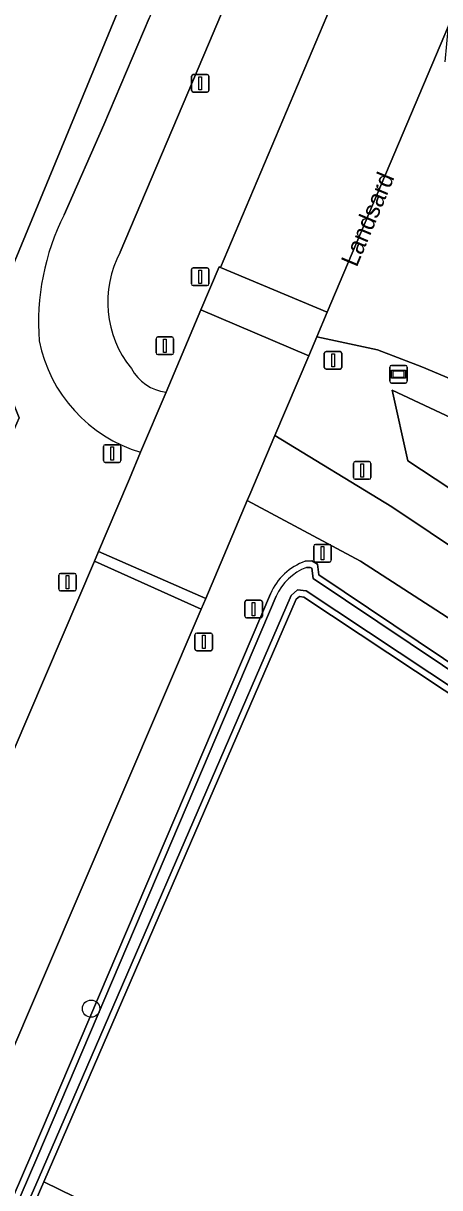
# Model space of a CAD drawing. Extents: x 155209 to 156748, y 385356 to 388487.
# Drawn here: x 155999.5 to 156023.1, y 386144.1 to 386210 of the extents above; entities that cross this region are included whole.
import ezdxf

# ---------------------------------------------------------------- set-up
doc = ezdxf.new("R2010")
doc.units = 0
for name, color, linetype in [('IMGEO_Berm_groen', 7, 'Continuous'), ('IMGEO_Boom', 7, 'Continuous'), ('IMGEO_Erf', 7, 'Continuous'), ('IMGEO_Fietspad_gesloten', 7, 'Continuous'), ('IMGEO_Groenvoorziening', 7, 'Continuous'), ('IMGEO_Hek', 7, 'Continuous'), ('IMGEO_Lichtmast', 7, 'Continuous'), ('IMGEO_Loofbos', 7, 'Continuous'), ('IMGEO_Naaldbos', 7, 'Continuous'), ('IMGEO_Oever', 7, 'Continuous'), ('IMGEO_Openbare_ruimte_label', 7, 'Continuous'), ('IMGEO_Rijbaan_lokaal_gesloten', 7, 'Continuous'), ('IMGEO_Rijbaan_lokaal_open', 7, 'Continuous'), ('IMGEO_Straatnaambord', 7, 'Continuous'), ('IMGEO_Verkeersbordpaal', 7, 'Continuous'), ('IMGEO_Waterloop', 7, 'Continuous')]:
    doc.layers.add(name, color=color, linetype=linetype)

msp = doc.modelspace()

# ---------------------------------------------------------------- linework, layer by layer
at = {"layer": 'IMGEO_Berm_groen'}
for points in [[(156017.719, 386241.801), (155997.339, 386192.467), (155999.279, 386187.649), (155999.017, 386187.05), (155959.302, 386096.168), (155916.981, 385994.929), (155916.273, 385993.234), (155920.084, 385991.513), (155920.814, 385993.21), (155925.378, 386003.819), (155927.744, 386002.822), (155959.53, 386076.883), (155989.702, 386147.215), (156003.535, 386179.533)], [(156001.816, 386199.144), (156004.066, 386204.243), (156006.628, 386210.275)], [(156067.725, 386171.243), (156063.134, 386173.252), (156022.073, 386190.539), (156019.563, 386191.511), (156016.121, 386192.247), (156015.665, 386191.171), (156013.752, 386186.657), (156020.382, 386182.613), (156026.946, 386178.211), (156056.89, 386158.505), (156068.33, 386150.873), (156070.659, 386149.306), (156072.014, 386151.81), (156034.567, 386176.468), (156033.731, 386175.202), (156032.227, 386176.195), (156033.061, 386177.459), (156021.284, 386185.214), (156020.389, 386189.219)], [(156020.389, 386189.219), (156031.664, 386183.929), (156073.255, 386164.351), (156077.439, 386161.836), (156079.419, 386165.495)], [(156003.535, 386179.533), (156003.773, 386180.094), (156004.801, 386182.521), (156005.515, 386184.205), (156006.15, 386185.705)], [(156049.551, 386158.857), (156049.349, 386159.56), (156025.311, 386175.189), (156018.608, 386179.531), (156012.192, 386182.976), (156009.838, 386177.421), (156009.585, 386176.823), (155984.914, 386119.233), (155965.644, 386074.344), (155949.137, 386035.922), (155952.015, 386034.682), (156000, 386146.004)], [(156015.467, 386179.533), (156015.839, 386179.549), (156016.169, 386179.377), (156016.248, 386178.762), (156028.926, 386170.26), (156049.296, 386156.966), (156049.474, 386156.85)], [(156000, 386146.004), (156013.501, 386177.695)]]:
    msp.add_lwpolyline(points, dxfattribs=at)
for centre, radius, start, end in [((156014.042, 386193.021), 13.673, 153.3985, 184.23817), ((156008.54, 386193.651), 8.298, 191.40063, 253.2588), ((156016.601, 386176.349), 3.38, 109.60897, 156.53662)]:
    msp.add_arc(centre, radius, start, end, dxfattribs=at)
at = {"layer": 'IMGEO_Boom'}
msp.add_circle((156003.346, 386154.198), 0.489, dxfattribs=at)
at = {"layer": 'IMGEO_Erf'}
msp.add_lwpolyline([(156066.005, 386142.456), (156065.663, 386144.592), (156050.195, 386154.65), (156050.562, 386155.229), (156050.971, 386155.873), (156050.765, 386156.008), (156050.72, 386155.966), (156049.405, 386156.687), (156049.474, 386156.85), (156049.296, 386156.966), (156048.886, 386156.32), (156048.518, 386155.741), (156032.854, 386165.927), (156015.392, 386177.509), (156015.147, 386177.545), (156014.962, 386177.381), (156000.676, 386144.39), (156006.735, 386141.433)], dxfattribs=at)
at = {"layer": 'IMGEO_Fietspad_gesloten'}
for points in [[(156139.321, 386522.401), (156125.525, 386490.134), (156111.258, 386456.764), (156087.976, 386402.172), (156066.589, 386351.85), (156054.716, 386323.807), (156054.538, 386323.386), (156042.977, 386296.079), (156023.427, 386249.93), (156022.289, 386247.244), (156019.639, 386240.989), (156006.628, 386210.275), (156004.066, 386204.243), (156001.816, 386199.144)], [(156004.996, 386197.039), (156010.003, 386208.816), (156023.008, 386239.564), (156046.408, 386294.89), (156058.063, 386322.415), (156069.84, 386350.227), (156091.234, 386400.622), (156114.612, 386455.401), (156142.588, 386521.008)], [(156006.15, 386185.705), (156007.591, 386189.104)]]:
    msp.add_lwpolyline(points, dxfattribs=at)
for centre, radius, start, end in [((156014.042, 386193.021), 13.673, 153.3985, 184.23817), ((156010.253, 386194.215), 5.968, 151.75594, 219.16082), ((156008.54, 386193.651), 8.298, 191.40063, 253.2588), ((156007.906, 386191.675), 2.59, 208.32341, 263.01421)]:
    msp.add_arc(centre, radius, start, end, dxfattribs=at)
at = {"layer": 'IMGEO_Groenvoorziening'}
for points in [[(156007.591, 386189.104), (156009.569, 386193.772), (156010.599, 386196.203), (156010.669, 386196.174), (156028.113, 386237.404), (156051.194, 386291.958), (156074.965, 386348.058), (156088.146, 386379.283), (156100.534, 386408.284), (156128.809, 386474.423), (156158.862, 386544.699), (156160.628, 386548.864)], [(156142.588, 386521.008), (156114.612, 386455.401), (156091.234, 386400.622), (156069.84, 386350.227), (156058.063, 386322.415), (156046.408, 386294.89), (156023.008, 386239.564), (156010.003, 386208.816), (156004.996, 386197.039)]]:
    msp.add_lwpolyline(points, dxfattribs=at)
msp.add_lwpolyline([(156031.664, 386183.929), (156020.389, 386189.219), (156021.284, 386185.214), (156033.061, 386177.459), (156033.106, 386177.526), (156034.61, 386176.533), (156034.567, 386176.468), (156072.014, 386151.81), (156073.332, 386154.247), (156077.439, 386161.836), (156073.255, 386164.351)], close=True, dxfattribs=at)
for centre, radius, start, end in [((156010.253, 386194.215), 5.968, 151.75594, 219.16082), ((156007.906, 386191.675), 2.59, 208.32341, 263.01421)]:
    msp.add_arc(centre, radius, start, end, dxfattribs=at)
at = {"layer": 'IMGEO_Hek'}
msp.add_lwpolyline([(155979.683, 386081.47), (155987.477, 386099.578), (156000, 386126.796), (156006.735, 386141.433), (156000.676, 386144.39)], dxfattribs=at)
at = {"layer": 'IMGEO_Lichtmast'}
for p, q in [((156009.031, 386206.195), (156009.031, 386206.995)), ((156009.031, 386206.995), (156009.031, 386206.195)), ((156009.131, 386207.095), (156009.921, 386207.095)), ((156009.921, 386207.095), (156009.131, 386207.095)), ((156010.021, 386206.995), (156010.021, 386206.195)), ((156010.021, 386206.195), (156010.021, 386206.995)), ((156009.921, 386206.095), (156009.131, 386206.095)), ((156009.131, 386206.095), (156009.921, 386206.095)), ((156012.053, 386176.426), (156012.053, 386177.226)), ((156012.053, 386177.226), (156012.053, 386176.426)), ((156012.153, 386177.326), (156012.943, 386177.326)), ((156012.943, 386177.326), (156012.153, 386177.326)), ((156013.043, 386177.226), (156013.043, 386176.426)), ((156013.043, 386176.426), (156013.043, 386177.226)), ((156012.943, 386176.326), (156012.153, 386176.326)), ((156012.153, 386176.326), (156012.943, 386176.326))]:
    msp.add_line(p, q, dxfattribs=at)
for points in [[(156009.451, 386206.97), (156009.601, 386206.97), (156009.601, 386206.22), (156009.451, 386206.22), (156009.451, 386206.97)], [(156012.473, 386177.201), (156012.623, 386177.201), (156012.623, 386176.451), (156012.473, 386176.451), (156012.473, 386177.201)]]:
    msp.add_lwpolyline(points, dxfattribs=at)
for centre, start, end in [((156009.131, 386206.995), 90, 180), ((156009.131, 386206.995), 90, 180), ((156009.921, 386206.995), 0, 90), ((156009.921, 386206.995), 360, 90), ((156009.131, 386206.195), 180, 270), ((156009.131, 386206.195), 180, 270), ((156009.921, 386206.195), 270, 0), ((156009.921, 386206.195), 270, 0), ((156012.153, 386177.226), 90, 180), ((156012.153, 386177.226), 90, 180), ((156012.943, 386177.226), 0, 90), ((156012.943, 386177.226), 360, 90), ((156012.153, 386176.426), 180, 270), ((156012.153, 386176.426), 180, 270), ((156012.943, 386176.426), 270, 0), ((156012.943, 386176.426), 270, 0)]:
    msp.add_arc(centre, 0.1, start, end, dxfattribs=at)
at = {"layer": 'IMGEO_Loofbos'}
msp.add_lwpolyline([(155999.017, 386187.05), (155999.279, 386187.649), (155997.339, 386192.467), (156017.719, 386241.801), (156020.329, 386248.119), (156016.112, 386250), (156000, 386257.19), (155899.336, 386302.109), (155849.188, 386325.166), (155836.76, 386296.062), (155825.154, 386268.112)], dxfattribs=at)
at = {"layer": 'IMGEO_Naaldbos'}
msp.add_lwpolyline([(155979.683, 386081.47), (155987.477, 386099.578), (156000, 386126.796), (156006.735, 386141.433), (156000.676, 386144.39), (156000, 386142.83), (155975.488, 386085.88), (155975.714, 386085.504)], close=True, dxfattribs=at)
at = {"layer": 'IMGEO_Oever'}
for points in [[(156000, 386142.83), (156000.676, 386144.39), (156014.962, 386177.381), (156015.147, 386177.545), (156015.392, 386177.509), (156032.854, 386165.927), (156048.518, 386155.741), (156048.886, 386156.32), (156049.296, 386156.966), (156028.926, 386170.26), (156016.248, 386178.762), (156016.169, 386179.377), (156015.839, 386179.549), (156015.467, 386179.533)], [(156015.538, 386179.179), (156015.759, 386179.188), (156015.839, 386179.147), (156015.914, 386178.556), (156028.729, 386169.962), (156048.806, 386156.86), (156048.585, 386156.512), (156048.41, 386156.237), (156033.05, 386166.225), (156015.523, 386177.851), (156015.034, 386177.922), (156014.666, 386177.596), (156000.348, 386144.532), (155999.672, 386142.972), (155975.088, 386085.853), (155975.313, 386085.477), (155942.794, 386010.259)], [(156013.501, 386177.695), (156000, 386146.004), (155952.015, 386034.682), (155941.599, 386010.515), (155942.719, 386009.186), (155975.714, 386085.504), (155975.488, 386085.88), (156000, 386142.83)], [(155942.794, 386010.259), (155942.162, 386010.92), (156000.328, 386145.863), (156013.829, 386177.554)]]:
    msp.add_lwpolyline(points, dxfattribs=at)
for centre, radius, start, end in [((156016.601, 386176.349), 3.38, 109.60897, 156.53662), ((156016.617, 386176.333), 3.044, 110.76625, 156.34723)]:
    msp.add_arc(centre, radius, start, end, dxfattribs=at)
at = {"layer": 'IMGEO_Rijbaan_lokaal_gesloten'}
for points in [[(156160.628, 386548.864), (156158.862, 386544.699), (156128.809, 386474.423), (156100.534, 386408.284), (156088.146, 386379.283), (156074.965, 386348.058), (156051.194, 386291.958), (156028.113, 386237.404), (156010.669, 386196.174), (156016.712, 386193.643), (156023.573, 386209.847), (156034.159, 386234.847), (156057.345, 386289.662), (156080.926, 386345.397), (156094.197, 386376.746), (156106.547, 386405.649)], [(156023.385, 386207.816), (156023.573, 386209.847), (156016.712, 386193.643), (156016.121, 386192.247), (156019.563, 386191.511), (156022.073, 386190.539), (156063.134, 386173.252), (156067.725, 386171.243)], [(156148.477, 386094.745), (156078.082, 386144.223), (156076.416, 386145.394), (156074.85, 386146.487), (156073.573, 386147.346), (156070.659, 386149.306), (156068.33, 386150.873), (156056.89, 386158.505), (156026.946, 386178.211), (156020.382, 386182.613), (156013.752, 386186.657), (156012.339, 386183.322), (156012.192, 386182.976), (156018.608, 386179.531), (156025.311, 386175.189), (156049.349, 386159.56), (156053.498, 386156.729), (156055.217, 386155.797), (156067.905, 386147.283), (156068.865, 386146.585), (156072.75, 386143.917)], [(155944.241, 386024.526), (155949.137, 386035.922), (155965.644, 386074.344), (155984.914, 386119.233), (156009.585, 386176.823), (156003.535, 386179.533), (155989.702, 386147.215), (155959.53, 386076.883), (155927.744, 386002.822), (155923, 385991.79), (155918.964, 385982.464), (155913.394, 385969.476), (155908.982, 385959.227), (155875.912, 385882.637)]]:
    msp.add_lwpolyline(points, dxfattribs=at)
at = {"layer": 'IMGEO_Rijbaan_lokaal_open'}
for points in [[(156010.669, 386196.174), (156010.599, 386196.203), (156009.569, 386193.772), (156015.665, 386191.171), (156016.121, 386192.247), (156016.712, 386193.643)], [(156013.752, 386186.657), (156015.665, 386191.171), (156009.569, 386193.772), (156007.591, 386189.104), (156006.15, 386185.705), (156005.515, 386184.205), (156004.801, 386182.521), (156003.773, 386180.094), (156009.838, 386177.421), (156012.192, 386182.976), (156012.339, 386183.322)], [(156003.773, 386180.094), (156003.535, 386179.533), (156009.585, 386176.823), (156009.838, 386177.421)]]:
    msp.add_lwpolyline(points, close=True, dxfattribs=at)
at = {"layer": 'IMGEO_Straatnaambord'}
for p, q in [((156020.256, 386189.723), (156020.256, 386190.523)), ((156020.256, 386190.523), (156020.256, 386189.723)), ((156020.356, 386190.623), (156021.146, 386190.623)), ((156021.146, 386190.623), (156020.356, 386190.623)), ((156021.246, 386190.523), (156021.246, 386189.723)), ((156021.246, 386189.723), (156021.246, 386190.523)), ((156021.146, 386189.623), (156020.356, 386189.623)), ((156020.356, 386189.623), (156021.146, 386189.623))]:
    msp.add_line(p, q, dxfattribs=at)
for points in [[(156020.357, 386190.355), (156021.145, 386190.355), (156021.145, 386189.891), (156020.357, 386189.891), (156020.357, 386190.355)], [(156020.422, 386190.29), (156020.422, 386189.956), (156021.08, 386189.956), (156021.08, 386190.29), (156020.422, 386190.29)]]:
    msp.add_lwpolyline(points, dxfattribs=at)
for centre, start, end in [((156020.356, 386190.523), 90, 180), ((156020.356, 386190.523), 90, 180), ((156021.146, 386190.523), 0, 90), ((156021.146, 386190.523), 360, 90), ((156020.356, 386189.723), 180, 270), ((156020.356, 386189.723), 180, 270), ((156021.146, 386189.723), 270, 0), ((156021.146, 386189.723), 270, 0)]:
    msp.add_arc(centre, 0.1, start, end, dxfattribs=at)
at = {"layer": 'IMGEO_Verkeersbordpaal'}
for p, q in [((156009.029, 386195.244), (156009.029, 386196.044)), ((156009.029, 386196.044), (156009.029, 386195.244)), ((156009.129, 386196.144), (156009.919, 386196.144)), ((156009.919, 386196.144), (156009.129, 386196.144)), ((156010.019, 386196.044), (156010.019, 386195.244)), ((156010.019, 386195.244), (156010.019, 386196.044)), ((156009.919, 386195.144), (156009.129, 386195.144)), ((156009.129, 386195.144), (156009.919, 386195.144)), ((156007.025, 386191.334), (156007.025, 386192.134)), ((156007.025, 386192.134), (156007.025, 386191.334)), ((156007.125, 386192.234), (156007.915, 386192.234)), ((156007.915, 386192.234), (156007.125, 386192.234)), ((156008.015, 386192.134), (156008.015, 386191.334)), ((156008.015, 386191.334), (156008.015, 386192.134)), ((156016.65, 386191.41), (156017.44, 386191.41)), ((156017.44, 386191.41), (156016.65, 386191.41)), ((156007.915, 386191.234), (156007.125, 386191.234)), ((156007.125, 386191.234), (156007.915, 386191.234)), ((156016.55, 386190.51), (156016.55, 386191.31)), ((156016.55, 386191.31), (156016.55, 386190.51)), ((156017.54, 386191.31), (156017.54, 386190.51)), ((156017.54, 386190.51), (156017.54, 386191.31)), ((156017.44, 386190.41), (156016.65, 386190.41)), ((156016.65, 386190.41), (156017.44, 386190.41)), ((156004.147, 386186.134), (156004.937, 386186.134)), ((156004.937, 386186.134), (156004.147, 386186.134)), ((156004.047, 386185.234), (156004.047, 386186.034)), ((156004.047, 386186.034), (156004.047, 386185.234)), ((156005.037, 386186.034), (156005.037, 386185.234)), ((156005.037, 386185.234), (156005.037, 386186.034)), ((156004.937, 386185.134), (156004.147, 386185.134)), ((156004.147, 386185.134), (156004.937, 386185.134)), ((156018.196, 386184.277), (156018.196, 386185.077)), ((156018.196, 386185.077), (156018.196, 386184.277)), ((156018.296, 386185.177), (156019.086, 386185.177)), ((156019.086, 386185.177), (156018.296, 386185.177)), ((156019.186, 386185.077), (156019.186, 386184.277)), ((156019.186, 386184.277), (156019.186, 386185.077)), ((156019.086, 386184.177), (156018.296, 386184.177)), ((156018.296, 386184.177), (156019.086, 386184.177)), ((156015.953, 386179.59), (156015.953, 386180.39)), ((156015.953, 386180.39), (156015.953, 386179.59)), ((156016.053, 386180.49), (156016.843, 386180.49)), ((156016.843, 386180.49), (156016.053, 386180.49)), ((156016.943, 386180.39), (156016.943, 386179.59)), ((156016.943, 386179.59), (156016.943, 386180.39)), ((156016.843, 386179.49), (156016.053, 386179.49)), ((156016.053, 386179.49), (156016.843, 386179.49)), ((156001.614, 386178.849), (156002.404, 386178.849)), ((156002.404, 386178.849), (156001.614, 386178.849)), ((156001.514, 386177.949), (156001.514, 386178.749)), ((156001.514, 386178.749), (156001.514, 386177.949)), ((156002.504, 386178.749), (156002.504, 386177.949)), ((156002.504, 386177.949), (156002.504, 386178.749)), ((156002.404, 386177.849), (156001.614, 386177.849)), ((156001.614, 386177.849), (156002.404, 386177.849)), ((156009.227, 386174.564), (156009.227, 386175.364)), ((156009.227, 386175.364), (156009.227, 386174.564)), ((156009.327, 386175.464), (156010.117, 386175.464)), ((156010.117, 386175.464), (156009.327, 386175.464)), ((156010.217, 386175.364), (156010.217, 386174.564)), ((156010.217, 386174.564), (156010.217, 386175.364)), ((156010.117, 386174.464), (156009.327, 386174.464)), ((156009.327, 386174.464), (156010.117, 386174.464))]:
    msp.add_line(p, q, dxfattribs=at)
for points in [[(156009.449, 386196.019), (156009.599, 386196.019), (156009.599, 386195.269), (156009.449, 386195.269), (156009.449, 386196.019)], [(156007.445, 386192.109), (156007.595, 386192.109), (156007.595, 386191.359), (156007.445, 386191.359), (156007.445, 386192.109)], [(156016.97, 386191.285), (156017.12, 386191.285), (156017.12, 386190.535), (156016.97, 386190.535), (156016.97, 386191.285)], [(156004.467, 386186.009), (156004.617, 386186.009), (156004.617, 386185.259), (156004.467, 386185.259), (156004.467, 386186.009)], [(156018.616, 386185.052), (156018.766, 386185.052), (156018.766, 386184.302), (156018.616, 386184.302), (156018.616, 386185.052)], [(156016.373, 386180.365), (156016.523, 386180.365), (156016.523, 386179.615), (156016.373, 386179.615), (156016.373, 386180.365)], [(156001.934, 386178.724), (156002.084, 386178.724), (156002.084, 386177.974), (156001.934, 386177.974), (156001.934, 386178.724)], [(156009.647, 386175.339), (156009.797, 386175.339), (156009.797, 386174.589), (156009.647, 386174.589), (156009.647, 386175.339)]]:
    msp.add_lwpolyline(points, dxfattribs=at)
for centre, start, end in [((156009.129, 386196.044), 90, 180), ((156009.129, 386196.044), 90, 180), ((156009.919, 386196.044), 0, 90), ((156009.919, 386196.044), 360, 90), ((156009.129, 386195.244), 180, 270), ((156009.129, 386195.244), 180, 270), ((156009.919, 386195.244), 270, 0), ((156009.919, 386195.244), 270, 0), ((156007.125, 386192.134), 90, 180), ((156007.125, 386192.134), 90, 180), ((156007.915, 386192.134), 0, 90), ((156007.915, 386192.134), 360, 90), ((156016.65, 386191.31), 90, 180), ((156016.65, 386191.31), 90, 180), ((156017.44, 386191.31), 0, 90), ((156017.44, 386191.31), 360, 90), ((156007.125, 386191.334), 180, 270), ((156007.125, 386191.334), 180, 270), ((156007.915, 386191.334), 270, 0), ((156007.915, 386191.334), 270, 0), ((156016.65, 386190.51), 180, 270), ((156016.65, 386190.51), 180, 270), ((156017.44, 386190.51), 270, 0), ((156017.44, 386190.51), 270, 0), ((156004.147, 386186.034), 90, 180), ((156004.147, 386186.034), 90, 180), ((156004.937, 386186.034), 0, 90), ((156004.937, 386186.034), 360, 90), ((156004.147, 386185.234), 180, 270), ((156004.147, 386185.234), 180, 270), ((156004.937, 386185.234), 270, 0), ((156004.937, 386185.234), 270, 0), ((156018.296, 386185.077), 90, 180), ((156018.296, 386185.077), 90, 180), ((156019.086, 386185.077), 0, 90), ((156019.086, 386185.077), 360, 90), ((156018.296, 386184.277), 180, 270), ((156018.296, 386184.277), 180, 270), ((156019.086, 386184.277), 270, 0), ((156019.086, 386184.277), 270, 0), ((156016.053, 386180.39), 90, 180), ((156016.053, 386180.39), 90, 180), ((156016.843, 386180.39), 0, 90), ((156016.843, 386180.39), 360, 90), ((156016.053, 386179.59), 180, 270), ((156016.053, 386179.59), 180, 270), ((156016.843, 386179.59), 270, 0), ((156016.843, 386179.59), 270, 0), ((156001.614, 386178.749), 90, 180), ((156001.614, 386178.749), 90, 180), ((156002.404, 386178.749), 0, 90), ((156002.404, 386178.749), 360, 90), ((156001.614, 386177.949), 180, 270), ((156001.614, 386177.949), 180, 270), ((156002.404, 386177.949), 270, 0), ((156002.404, 386177.949), 270, 0), ((156009.327, 386175.364), 90, 180), ((156009.327, 386175.364), 90, 180), ((156010.117, 386175.364), 0, 90), ((156010.117, 386175.364), 360, 90), ((156009.327, 386174.564), 180, 270), ((156009.327, 386174.564), 180, 270), ((156010.117, 386174.564), 270, 0), ((156010.117, 386174.564), 270, 0)]:
    msp.add_arc(centre, 0.1, start, end, dxfattribs=at)
at = {"layer": 'IMGEO_Waterloop'}
msp.add_lwpolyline([(156013.829, 386177.554), (156000.328, 386145.863), (155942.162, 386010.92), (155942.794, 386010.259), (155975.313, 386085.477), (155975.088, 386085.853), (155999.672, 386142.972), (156000.348, 386144.532), (156014.666, 386177.596), (156015.034, 386177.922), (156015.523, 386177.851), (156033.05, 386166.225), (156048.41, 386156.237), (156048.585, 386156.512), (156048.806, 386156.86), (156028.729, 386169.962), (156015.914, 386178.556), (156015.839, 386179.147), (156015.759, 386179.188), (156015.538, 386179.179)], dxfattribs=at)
msp.add_arc((156016.617, 386176.333), 3.044, 110.76625, 156.34723, dxfattribs=at)

# ---------------------------------------------------------------- texts
at = {"layer": 'IMGEO_Openbare_ruimte_label'}
msp.add_text('Landsard', height=1, rotation=67.23027, dxfattribs=at).set_placement((156018.383, 386196.142))

doc.saveas('drawing.dxf')
